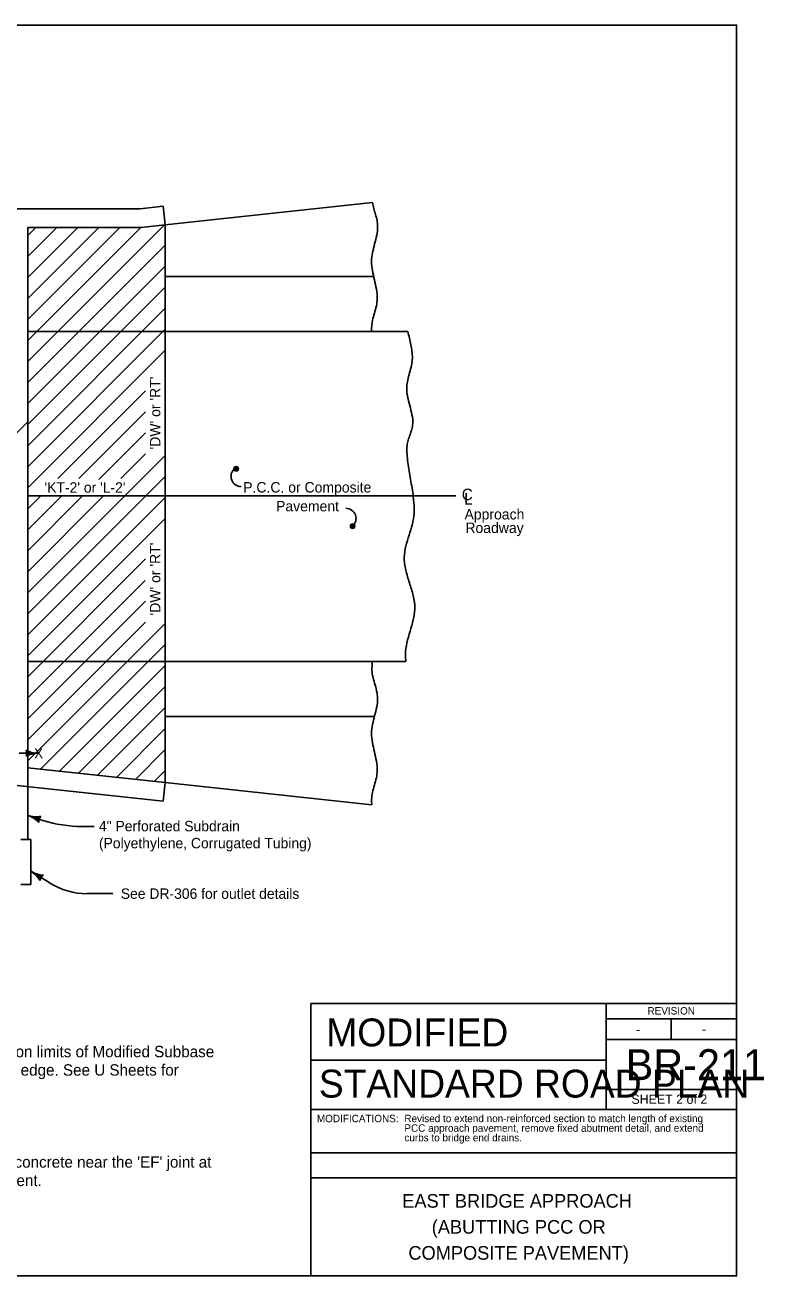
# Model space of a CAD drawing. Extents: x 5546 to 81668, y 3174 to 15999.
# Drawn here: x 26518 to 27712, y 7924 to 9944 of the extents above; entities that cross this region are included whole.
import ezdxf

# ---------------------------------------------------------------- set-up
doc = ezdxf.new("R2010")
doc.units = 0
for name, color, linetype in [('Level 61', 7, 'Continuous'), ('PS_BOLT', 7, 'Continuous'), ('PS_DIM', 7, 'Continuous'), ('Table Border', 7, 'Continuous'), ('tdCoLegendTitle', 7, 'Continuous'), ('tdCoShieldUsRte', 7, 'Continuous')]:
    doc.layers.add(name, color=color, linetype=linetype)

msp = doc.modelspace()

# ---------------------------------------------------------------- linework, layer by layer
at = {"layer": 'Level 61'}
msp.add_lwpolyline([(24532.5, 9944), (27667.5, 9944), (27667.5, 7924), (24532.5, 7924)], close=True, dxfattribs=at)
at = {"layer": 'PS_BOLT'}
for p, q in [((26539.5, 8768.1), (26508.2, 8768.1)), ((26629.4, 8649.8), (26609.8, 8649.8)), ((26557.9, 8558.6), (26527.3, 8577.8)), ((26659.5, 8541.4), (26617.9, 8541.4))]:
    msp.add_line(p, q, dxfattribs=at)
for centre, radius, start, end in [((26867.2, 9215.1), 16.5, 131.3092, 270), ((27036.2, 9147.2), 16.5, 311.309, 90), ((26609.8, 8855.4), 205.6, 252.1406, 270), ((26617.9, 8654.4), 113.1, 237.9168, 270)]:
    msp.add_arc(centre, radius, start, end, dxfattribs=at)
at = {"layer": 'PS_DIM'}
for p, q in [((25553.2, 9647.3), (26704.1, 9647.3)), ((26704.1, 9647.3), (26741, 9651.3)), ((26744.2, 9621.4), (26741, 9651.3)), ((26522.2, 9400.5), (26743, 9621.3)), ((26522.2, 9434.4), (26705, 9617.3)), ((26522.2, 9468.4), (26671.1, 9617.3)), ((26522.2, 9502.3), (26637.2, 9617.3)), ((26522.2, 9536.3), (26603.2, 9617.3)), ((26522.2, 9570.2), (26569.3, 9617.3)), ((26522.2, 9604.1), (26535.3, 9617.3)), ((26522.2, 9366.6), (26744.2, 9588.6)), ((26522.2, 9332.6), (26744.2, 9554.6)), ((26522.2, 9298.7), (26744.2, 9520.7)), ((26522.2, 9264.7), (26744.2, 9486.7)), ((26522.2, 9230.8), (26744.2, 9452.8)), ((26522.2, 9448.9), (26744.2, 9449)), ((26522.2, 9196.8), (26744.2, 9418.8)), ((26570.8, 9211.6), (26712.3, 9353.1)), ((26604.9, 9211.7), (26712.4, 9319.2)), ((26078.2, 8859.5), (26522.2, 9303.5)), ((26637, 9209.9), (26712.6, 9285.4)), ((26522.2, 9027.1), (26744.2, 9249.1)), ((26672.8, 9211.8), (26712.5, 9251.4)), ((26522.2, 8993.2), (26744.2, 9215.2)), ((26522.2, 9061.1), (26644.6, 9183.5)), ((26522.2, 9095), (26610.6, 9183.5)), ((26522.2, 9129), (26576.6, 9183.4)), ((26522.2, 9162.9), (26542.6, 9183.4)), ((26522.2, 8959.3), (26744.2, 9181.3)), ((26522.2, 8925.3), (26744.2, 9147.3)), ((26522.2, 8891.4), (26712.7, 9082)), ((26522.2, 8857.4), (26711.8, 9047.1)), ((26522.2, 8823.5), (26712.3, 9013.6)), ((26522.2, 8789.6), (26712.4, 8979.8)), ((26522.2, 8755.6), (26744.2, 8977.6)), ((26522.2, 8744.6), (26522.2, 8955)), ((26542.8, 8742.3), (26744.2, 8943.7)), ((26522.2, 8916.1), (26744.2, 8916.2)), ((26573.5, 8739), (26744.2, 8909.7)), ((26604.1, 8735.8), (26744.2, 8875.8)), ((26634.8, 8732.5), (26744.2, 8841.8)), ((26665.4, 8729.2), (26744.2, 8807.9)), ((26696.1, 8725.9), (26744.2, 8774)), ((26522.2, 8744.6), (26522.2, 8628.8)), ((26726.7, 8722.6), (26744.2, 8740)), ((26741, 8690.9), (26490, 8717.8)), ((26744.2, 8720.7), (26741, 8690.9)), ((26546.7, 8659.7), (26522.2, 8667.7)), ((26522.2, 8667.7), (26541, 8661.6)), ((26527.3, 8628.8), (26510.8, 8628.8)), ((26527.3, 8628.8), (26527.3, 8556.4)), ((26527.3, 8577.8), (26544, 8567.3)), ((26527.3, 8556.4), (26510.8, 8556.4))]:
    msp.add_line(p, q, dxfattribs=at)
for points in [[(26858.8, 9224.2), (26860, 9224.8), (26861.9, 9225.4), (26862.3, 9227.3), (26862, 9229), (26860.8, 9230.5), (26859, 9230.4), (26857.1, 9230.1), (26856.2, 9228.6), (26856, 9227), (26857.1, 9224.9), (26858.5, 9224.7), (26860.4, 9225.2), (26862, 9226.4), (26861.9, 9228.2), (26860.7, 9229.7), (26859, 9229.8), (26857.1, 9229.5), (26856.8, 9228.4), (26856.5, 9227.1), (26857.3, 9225.5), (26858.7, 9225.6), (26860.3, 9225.8), (26861.5, 9226.7), (26860.9, 9228.3), (26859.7, 9229.2), (26858.1, 9229.3), (26857.7, 9228.4), (26857.2, 9227.4), (26858, 9226.2), (26859.1, 9225.9), (26860.2, 9226.5), (26860.3, 9227.6), (26859.7, 9228.5), (26858.6, 9228.8), (26858.1, 9228.3), (26857.8, 9227.7), (26858.4, 9226.7), (26859.1, 9226.5), (26859.9, 9227), (26859.7, 9227.6), (26859.2, 9228), (26858.4, 9228), (26858.5, 9227.5), (26859.1, 9227.2)], [(27046.8, 9131.5), (27048, 9132), (27049.9, 9132.6), (27050.3, 9134.6), (27050, 9136.3), (27048.8, 9137.8), (27047, 9137.7), (27045.1, 9137.4), (27044.2, 9135.9), (27044, 9134.3), (27045.1, 9132.2), (27046.5, 9132), (27048.4, 9132.5), (27050, 9133.7), (27049.9, 9135.5), (27048.7, 9137), (27047, 9137.1), (27045.1, 9136.7), (27044.8, 9135.7), (27044.4, 9134.4), (27045.3, 9132.8), (27046.7, 9132.9), (27048.3, 9133.1), (27049.4, 9134), (27048.9, 9135.6), (27047.7, 9136.5), (27046.1, 9136.6), (27045.7, 9135.7), (27045.2, 9134.7), (27045.9, 9133.5), (27047.1, 9133.2), (27048.2, 9133.8), (27048.2, 9134.9), (27047.7, 9135.8), (27046.6, 9136), (27046.1, 9135.6), (27045.8, 9135), (27046.4, 9134), (27047.1, 9133.8), (27047.8, 9134.3), (27047.7, 9134.9), (27047.2, 9135.3), (27046.4, 9135.3), (27046.4, 9134.8), (27047.1, 9134.5)], [(26541.7, 8665.2), (26539.9, 8661.9), (26539.5, 8658.2), (26535.9, 8661.5), (26529.7, 8665.2), (26537.4, 8664.6), (26541, 8665), (26539.2, 8662.1), (26538.8, 8659.8), (26536.4, 8662), (26533, 8664.1), (26537.4, 8664), (26539.6, 8664), (26538.3, 8661.2), (26535.9, 8663.2), (26538.3, 8663.2), (26538, 8662.1), (26537.1, 8662.8)], [(26545.6, 8570.6), (26543.1, 8567.9), (26541.7, 8564.4), (26539.1, 8568.5), (26534, 8573.6), (26541.3, 8571.1), (26544.9, 8570.6), (26542.5, 8568.3), (26541.5, 8566.1), (26539.8, 8568.8), (26537, 8571.7), (26541.1, 8570.5), (26543.4, 8570), (26541.3, 8567.6), (26539.5, 8570.1), (26541.8, 8569.5), (26541.3, 8568.6), (26540.6, 8569.4)]]:
    msp.add_lwpolyline(points, dxfattribs=at)
for centre in [(26859.1, 9227.5), (27047.1, 9134.8)]:
    msp.add_circle(centre, 3.62, dxfattribs=at)
for centre, radius, start, end in [((26504.1, 8768.1), 16.3, 342.2666, 17.7333), ((26539.5, 8810.4), 42.3, 241.9275, 270), ((26539.5, 8725.8), 42.3, 90, 118.0725), ((26508.8, 8626.1), 43.7, 44.0691, 72.1415), ((26535.6, 8709.2), 43.7, 252.1415, 280.214), ((26557, 8656.4), 16.9, 144.4082, 179.8749), ((26504.1, 8540.8), 43.7, 29.8434, 57.9159), ((26550.5, 8614.8), 43.7, 237.9159, 265.9884), ((26558.3, 8558.3), 16.9, 130.1825, 165.6492)]:
    msp.add_arc(centre, radius, start, end, dxfattribs=at)
at = {"layer": 'Table Border'}
for p, q in [((26744.2, 9621.4), (27079.1, 9657.4)), ((26522.2, 9617.3), (26522.2, 8744.6)), ((26522.2, 9617.3), (26705.7, 9617.3)), ((26705.7, 9617.3), (26744.2, 9621.4)), ((26744.2, 9537.8), (26744.2, 9621.4)), ((26744.2, 9621.4), (26744.2, 9182.6)), ((26744.2, 9537.8), (26744.2, 9449)), ((27081.2, 9537.8), (26744.2, 9537.8)), ((26744.2, 9449), (27136.4, 9449)), ((26522.2, 9183.5), (26744.2, 9183.5)), ((26744.2, 9183.5), (27145.1, 9183.5)), ((26744.2, 9182.6), (26744.2, 8720.7)), ((27145.1, 9183.5), (27213.9, 9183.5)), ((26744.2, 8916.2), (27133.2, 8916.2)), ((26744.2, 8720.7), (26744.2, 8827.4)), ((27082.5, 8827.4), (26744.2, 8827.4)), ((26744.2, 8720.7), (26522.2, 8744.6)), ((27078.1, 8684.9), (26744.2, 8720.7))]:
    msp.add_line(p, q, dxfattribs=at)
for points in [[(27079.1, 9657.4), (27081.4, 9647.7), (27084.2, 9638.1), (27086.6, 9628.4), (27087.6, 9618.7), (27086.1, 9604.6), (27082.7, 9590.6), (27079.4, 9576.5), (27077.8, 9562.4), (27079.2, 9547.4), (27082.4, 9532.3), (27085.6, 9517.3), (27086.9, 9502.3), (27085.5, 9490.5), (27082.5, 9478.7), (27079.4, 9466.9), (27077.8, 9455.2), (27077.9, 9449)], [(27136.4, 9449), (27141.2, 9427.5), (27143, 9416.8), (27143.7, 9406.1), (27142.3, 9394.3), (27139.3, 9382.5), (27136.2, 9370.8), (27134.6, 9359), (27136, 9344.3), (27139.6, 9329.6), (27143.1, 9314.8), (27144.4, 9300.1), (27142.8, 9291.3), (27139.9, 9282.5), (27136.9, 9273.7), (27135.2, 9264.8), (27135.2, 9251.3), (27136.4, 9237.6), (27140.8, 9210.2), (27145.2, 9182.7), (27146.7, 9162.3), (27146.6, 9155.6), (27143.7, 9137.8), (27138.5, 9120.2), (27133.3, 9102.5), (27130.6, 9084.7), (27131.1, 9074.4), (27133, 9064), (27139, 9043.3), (27145, 9022.6), (27147.6, 9001.9), (27146.8, 8992.6), (27145.1, 8983.4), (27139.9, 8965), (27134.9, 8946.5), (27132.6, 8928), (27133.2, 8916.2)], [(27079.3, 8916.2), (27078.4, 8905.7), (27079.5, 8893.5), (27082.7, 8881.2), (27086, 8868.9), (27087.6, 8856.7), (27086.1, 8842.6), (27082.7, 8828.6), (27079.4, 8814.5), (27077.8, 8800.4), (27079.2, 8785.4), (27082.4, 8770.3), (27085.6, 8755.3), (27086.9, 8740.3), (27085.5, 8728.5), (27082.5, 8716.7), (27079.4, 8704.9), (27077.8, 8693.2), (27078.1, 8684.9)]]:
    msp.add_spline(points, degree=3, dxfattribs=at)
at = {"layer": 'tdCoLegendTitle'}
for p, q in [((27456.6, 8364), (27456.6, 8272.7)), ((27456.6, 8339.1), (27667.5, 8339.1)), ((27562.1, 8339.1), (27562.1, 8305.9)), ((27456.6, 8305.9), (27667.5, 8305.9)), ((26979.5, 8272.7), (27456.6, 8272.7)), ((27456.6, 8272.7), (27456.6, 8192.7)), ((27667.5, 8224.9), (27456.6, 8224.9)), ((26979.5, 8192.7), (27667.5, 8192.7)), ((26979.5, 8122.7), (27667.5, 8122.7)), ((26979.5, 8082.7), (27667.5, 8082.7)), ((26979.5, 8082.7), (27667.5, 8082.7))]:
    msp.add_line(p, q, dxfattribs=at)
msp.add_lwpolyline([(26979.5, 8364), (27667.5, 8364), (27667.5, 7924), (26979.5, 7924)], close=True, dxfattribs=at)

# ---------------------------------------------------------------- texts
at = {"layer": 'PS_BOLT'}
for p in [(26736.5, 9258.7), (26736.5, 8990.6)]:
    msp.add_text("'DW' or 'RT'", height=16.884, rotation=90, dxfattribs=at).set_placement(p)
for s, height, p in [("'KT-2' or 'L-2'", 16.8, (26549.4, 9188.9)), ('P.C.C. or Composite', 16.884, (26870.4, 9189.1)), ('C', 18.5, (27223.5, 9176.8)), ('Pavement', 16.88, (26923.5, 9158.7)), ('L', 18.5, (27227.4, 9169.6)), ('Approach', 16.88, (27228, 9145.6)), ('Roadway', 16.88, (27229.4, 9123.7)), ('X', 16, (26532.7, 8760.1)), ('4" Perforated Subdrain ', 16.8, (26637.3, 8642.1)), ('(Polyethylene, Corrugated Tubing)', 16.8, (26637.3, 8614.6)), ('See DR-306 for outlet details', 16.8, (26672.6, 8533)), ('Polymer Grid and excavation limits of Modified Subbase', 18.375, (26214.4, 8277.2)), ('2 feet outside of pavement edge. See U Sheets for', 18.375, (26214.4, 8247.5)), ('Place an "X" in the plastic concrete near the \'EF\' joint at', 18.375, (26214.4, 8098.9)), ('the outside edge of pavement.', 18.375, (26214.4, 8069.2))]:
    msp.add_text(s, height=height, dxfattribs=at).set_placement(p)
at = {"layer": 'tdCoLegendTitle'}
for s, height, p in [('REVISION', 12, (27523.6, 8346.2)), ('-', 15, (27505.1, 8314.7)), ('-', 15, (27611.6, 8315.1)), ('BR-211', 50, (27488.4, 8240.2)), ('STANDARD ROAD PLAN', 45.001, (26992.6, 8212.1)), ('SHEET 2 of 2', 15, (27497.6, 8202)), ('Revised to extend non-reinforced section to match length of existing ', 12, (27130.8, 8172.4)), ('PCC approach pavement, remove fixed abutment detail, and extend ', 12, (27130.8, 8156.9)), ('curbs to bridge end drains.', 12, (27130.8, 8141.4)), ('EAST BRIDGE APPROACH', 22, (27127.4, 8034.3)), ('(ABUTTING PCC OR', 22, (27175, 7992.3)), ('COMPOSITE PAVEMENT)', 22, (27137.3, 7950.3))]:
    msp.add_text(s, height=height, dxfattribs=at).set_placement(p)
at = {"layer": 'tdCoShieldUsRte'}
for s, height, p in [('MODIFIED', 45, (27004.6, 8294.8)), ('MODIFICATIONS:', 12, (26989.5, 8172.3))]:
    msp.add_text(s, height=height, dxfattribs=at).set_placement(p)

doc.saveas('drawing.dxf')
